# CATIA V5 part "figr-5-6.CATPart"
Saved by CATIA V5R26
Part number: Part1
Bounding box of the stored display mesh (mm): x 0 to 150, y -70 to 70, z -150 to 69.804
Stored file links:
  D:\_Deepak\CATIA\CATIA V5-6R2016_Deepak\Resources\Part files\Partfiles\c05_catia_v5_6r2016_prt\figr-5-6.CATPart
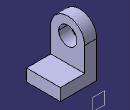
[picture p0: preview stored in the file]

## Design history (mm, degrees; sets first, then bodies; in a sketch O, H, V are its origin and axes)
Set1
  Plane1: type Offset, RefPlane face of Pad2, Offset 79, reversed
Body1 (main body)
  Sketch1 on yz-plane, origin (0, 0, 0), H (0, 1, 0), V (0, 0, 1)
    arc A1 centre (0, 0) radius 70 from (70, 0) to (-70, 0) ccw
    point P1 (70, 0)
    point P2 (-70, 0)
    line L1 (-70, 0) -> (-70, -150)
    line L2 (-70, -150) -> (70, -150)
    line L3 (70, -150) -> (70, 0)
    circle A2 centre (0, 0) radius 37.5
    radius A1 = 70
    radius A2 = 37.5
    distance O L2 = 150
    coincidence: P1 H, P2 H
    tangency: L1 A1, L3 A1
    horizontal: L2 H
  Pad1: profile Sketch1, direction (1, 0, 0), length 50
  Sketch2 on face of Pad1, origin (50, 0, 0), H (0, 1, 0), V (0, 0, 1)
    line L1 (-70, -150) -> (70, -150)
    line L2 (70, -150) -> (70, -100)
    line L3 (70, -100) -> (-70, -100)
    line L4 (-70, -100) -> (-70, -150)
    reference projected line E1 (-70, -150) -> (70, -150) from edge [face of Pad1 | face of Pad1]
    reference projected line E2 (-70, 0) -> (-70, -150) from edge [face of Pad1 | face of Pad1]
    reference projected line E3 (70, -150) -> (70, 0) from edge [face of Pad1 | face of Pad1]
    length L2 = 50
    horizontal: L1 H, L3 H
    vertical: L2 V, L4 V
    coincidence: L1 E1, E2 L4, L2 E3
  Pad2: profile Sketch2, direction (1, 0, 0), length 100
